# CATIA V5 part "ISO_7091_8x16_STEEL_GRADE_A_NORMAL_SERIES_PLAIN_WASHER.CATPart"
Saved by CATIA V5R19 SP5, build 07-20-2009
Part number: ISO 7091 WASHER 8x16 STEEL GRADE A PLAIN  NORMAL SERIES
Publications: "Mating Face", "Axis"
Bounding box of the stored display mesh (mm): x 0 to 2, y -8 to 8, z -8 to 8
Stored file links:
  Z:\UA\ATLAS\atlascar\ServoPiloto\dir\suportePotenciometro\ISO_7091_8x16_STEEL_GRADE_A_NORMAL_SERIES_PLAIN_WASHER.CATPart
  Z:\programs_vbox\Dassault Systemes\B19\intel_a\startup\components\MechanicalStandardParts\ISO_Standards\Design_Tables\ISO_7091_PLAIN_WASHER_GRADE_C_NORMAL_SERIES.txt
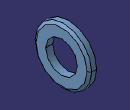
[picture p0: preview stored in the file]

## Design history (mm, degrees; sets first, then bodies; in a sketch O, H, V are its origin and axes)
Parameters
  d1_inside_dia = 9 mm
  d2_outside_dia = 16 mm
  h_max = 2 mm
  Nominal_dia = 8 mm
Body1 "PartBody" (main body)
  Sketch1 on yz-plane, origin (0, 0, 0), H (0, 1, 0), V (0, 0, 1)
    circle A1 centre (0, 0) radius 8
    circle A2 centre (0, 0) radius 4.5
    radius A1 = 8 {= d2_outside_dia /2}
    radius A2 = 4.5 {= d1_inside_dia /2}
  Pad1: profile Sketch1, direction (1, 0, 0), length 2 {= h_max}
  Chamfer1: length 0.75 {= 0.375*h_max}, angle 37.5, on edge [face of Pad1 | face of Pad1]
